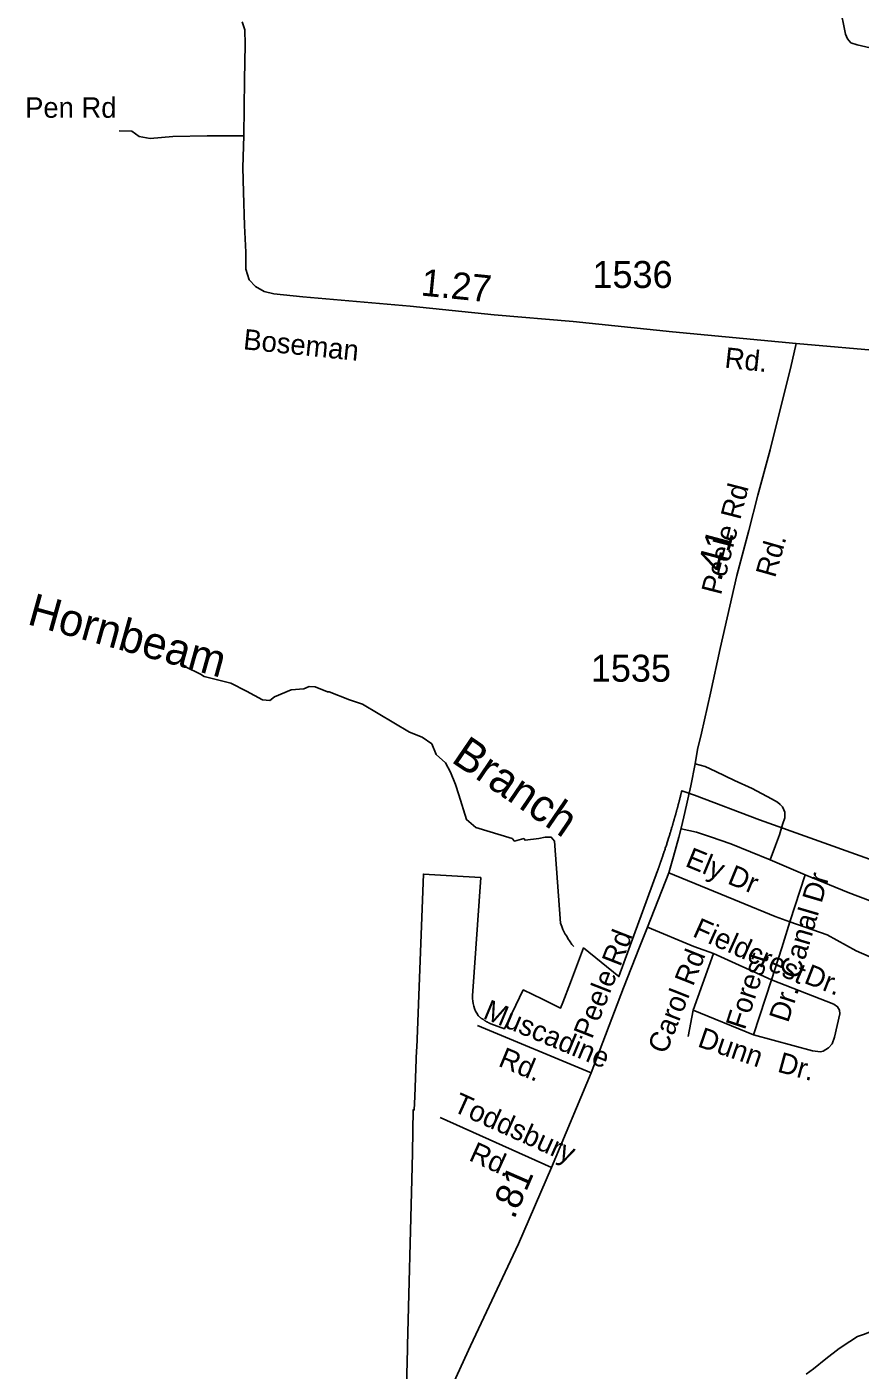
# Model space of a CAD drawing. Extents: x 2220236 to 2384410, y 720751 to 894131.
# Drawn here: x 2346680 to 2350546, y 819071 to 825303 of the extents above; entities that cross this region are included whole.
import ezdxf

# ---------------------------------------------------------------- set-up
doc = ezdxf.new("R2010")
doc.units = 0
doc.layers.add('Default', color=7, linetype='Continuous')

msp = doc.modelspace()

# ---------------------------------------------------------------- linework, layer by layer
at = {"layer": 'Default'}
for p, q in [((2350291.2, 821369.4), (2350129.4, 821438.5)), ((2350291.2, 821369.4), (2350219.5, 821151.6)), ((2349772, 820740.5), (2349866.2, 821004.9)), ((2349866.2, 821004.9), (2350134.7, 820881.7)), ((2350134.7, 820881.7), (2350051.7, 820626.8)), ((2349747.9, 820619.2), (2349772, 820740.5)), ((2350051.7, 820626.8), (2349772, 820740.5)), ((2348771.6, 820669.4), (2349298.2, 820449.8)), ((2348598.4, 820243), (2349115, 820011.9))]:
    msp.add_line(p, q, dxfattribs=at)
for points in [[(2350592.4, 825205.3), (2350533.1, 825219.2), (2350503.5, 825229.7), (2350487.8, 825247.2), (2350478.2, 825269.9), (2350452, 825399)], [(2350249.6, 823834.8), (2349675.4, 823888.9), (2349214.8, 823936.1), (2348848.4, 823967.5), (2348458.5, 824006.8), (2347960, 824051.3), (2347826.5, 824064.4), (2347780.7, 824074.9), (2347740.1, 824098.4), (2347711.3, 824129.9), (2347695.6, 824179.6), (2347695.6, 824258.2), (2347690.4, 824381.3), (2347685.2, 824535.8), (2347682.6, 824651), (2347687.1, 824797.6), (2347690.4, 825056.9), (2347693, 825221.8), (2347691.7, 825289.9), (2347678.6, 825326.6)], [(2347687.1, 824797.6), (2347517, 824797.6), (2347357.4, 824795), (2347252.7, 824784.5), (2347200.4, 824795), (2347166.4, 824818.6), (2347108.8, 824821.2)], [(2348429.1, 818509.2), (2348737.8, 819184.4), (2348961, 819657.6), (2349115, 820011.9), (2349298.2, 820449.8), (2349448.5, 820845.4), (2349523, 821034.2), (2349559.4, 821126.8), (2349658.3, 821378.4), (2349680.9, 821453.6), (2349705.3, 821544.4), (2349717.5, 821591.5), (2349733.2, 821657.9), (2349744.5, 821706.7), (2349760.2, 821782.7), (2349780.2, 821884.8), (2349791.6, 821950.3), (2349810, 822026.2), (2349851.8, 822212.1), (2349896.3, 822419), (2349974, 822757.7), (2350029.8, 822967.2), (2350071.8, 823130.2), (2350129.2, 823340.9), (2350178.1, 823539.8), (2350223.4, 823717.9), (2350249.6, 823834.8)], [(2351355.5, 823776.5), (2351251.8, 823781.3), (2351158.6, 823780.7), (2350975.6, 823783.5), (2350674.4, 823796.4), (2350249.6, 823834.8)], [(2347396.8, 822341.2), (2347409.1, 822336.8), (2347437.6, 822323.2), (2347463.7, 822311.1), (2347485.8, 822299.9), (2347502, 822289.7), (2347626.7, 822257.6), (2347699.2, 822221.4), (2347773.5, 822181.6), (2347806.6, 822178), (2347829.6, 822194.2), (2347905.7, 822226.8), (2347965.6, 822232.5), (2347989.5, 822242.4), (2348018.1, 822241.3), (2348074.2, 822218), (2348083.4, 822217.7), (2348177.5, 822181.6), (2348237.3, 822161.6), (2348454.7, 822031.2), (2348514.5, 822007.6)], [(2348514.5, 822007.6), (2348559.8, 821976.8), (2348579.7, 821927.9), (2348623.2, 821888.1), (2348645.6, 821845.1), (2348668.5, 821788.4), (2348684.8, 821739.5), (2348719.2, 821625.4), (2348762.7, 821589.1), (2348931.6, 821537.2), (2348943.3, 821525.2), (2348985.5, 821537.4), (2348991.4, 821529.4), (2349055.3, 821538.4), (2349084.2, 821543.8), (2349113.2, 821543.8), (2349127.7, 821525.7), (2349156.1, 821145.5), (2349162.3, 821129.4), (2349166.8, 821115.5), (2349172.6, 821103.6), (2349178.5, 821093.9), (2349184.8, 821084.4), (2349190.8, 821073.8), (2349201, 821057.8), (2349209.4, 821046), (2349217.3, 821036.5)], [(2349780.2, 821884.8), (2349826.7, 821872.4), (2349877.5, 821848.6), (2349963.9, 821807.5), (2350046.1, 821769.6), (2350135.8, 821722), (2350162.8, 821706.9), (2350175.8, 821696.1), (2350186.6, 821684.2), (2350193.1, 821671.2), (2350196.3, 821659.3), (2350197.4, 821643.1), (2350197.4, 821633.4), (2350186.6, 821603.1), (2350172.5, 821554.4), (2350154.2, 821505.8), (2350129.4, 821438.5)], [(2348437.8, 818870.9), (2348445.5, 819169.4), (2348446.2, 819184.9), (2348466.5, 819954.9), (2348469.5, 820077.6), (2348469.5, 820079.4), (2348472.8, 820280.1), (2348473.8, 820279.6), (2348477.2, 820277.9), (2348479.8, 820341.1), (2348488.2, 820556.1), (2348488.8, 820565.9), (2348504.5, 820971.7), (2348520.2, 821372.4), (2348704.8, 821361.1), (2348786, 821356.1), (2348748.2, 820807.2), (2348748.2, 820795.2), (2348749.2, 820783.2), (2348751, 820771.4), (2348753.8, 820759.8), (2348757.5, 820748.4), (2348762.2, 820737.3), (2348767.8, 820726.7), (2348774.2, 820716.5), (2348775.5, 820714.8), (2348776.2, 820714), (2348777.8, 820712.7), (2348780.8, 820710.2), (2348783.8, 820707.7), (2348785.5, 820706.4), (2348787, 820705.2), (2348788.5, 820704.1), (2348790, 820702.9), (2348791.8, 820701.7), (2348793.2, 820700.6), (2348795, 820699.4), (2348796.5, 820698.2), (2348798.2, 820697.2), (2348799.8, 820696.1), (2348801.5, 820695), (2348803, 820693.9), (2348804.8, 820692.9), (2348806.5, 820691.8), (2348808.2, 820690.8), (2348809.8, 820689.8), (2348811.5, 820688.8), (2348813.2, 820687.8), (2348815, 820686.9), (2348816.8, 820685.9), (2348818.5, 820685), (2348820.2, 820684.1), (2348822, 820683.2), (2348823.8, 820682.3), (2348825.5, 820681.4), (2348827.2, 820680.6), (2348829, 820679.8), (2348830.8, 820678.9), (2348832.2, 820678.4), (2348895.8, 820655.4), (2348983, 820835.1), (2349073, 820791.6), (2349156.8, 820751.1), (2349166.5, 820776.8), (2349202, 820870), (2349263, 821029.7), (2349427.2, 820896.9), (2349606.5, 821388.3), (2349607.5, 821390.6), (2349609, 821395.4), (2349610, 821397.7), (2349610.8, 821400.1), (2349611.8, 821402.4), (2349612.5, 821404.8), (2349613.2, 821407.1), (2349614.2, 821409.5), (2349615, 821411.8), (2349615.8, 821414.2), (2349616.8, 821416.6), (2349617.5, 821418.9), (2349618.2, 821421.2), (2349619.2, 821423.6), (2349620, 821426), (2349620.8, 821428.3), (2349621.8, 821430.7), (2349623.2, 821435.4), (2349624, 821437.8), (2349625, 821440.1), (2349626.5, 821444.9), (2349627.5, 821447.2), (2349628.2, 821449.6), (2349629, 821451.9), (2349630.5, 821456.7), (2349631.5, 821459.1), (2349633, 821463.8), (2349634.5, 821468.6), (2349635.5, 821470.9), (2349636.2, 821473.2), (2349637.8, 821478), (2349638.5, 821480.4), (2349639.5, 821482.8), (2349641, 821487.5), (2349642.5, 821492.2), (2349644, 821497), (2349644.8, 821499.4), (2349645.8, 821501.8), (2349647.2, 821506.5), (2349648.8, 821511.2), (2349649.5, 821513.7), (2349651, 821518.4), (2349652.5, 821523.2), (2349654, 821527.9), (2349655.5, 821532.7), (2349656.2, 821535.1), (2349657.8, 821539.9), (2349659.2, 821544.6), (2349660, 821547), (2349660.8, 821549.4), (2349661.5, 821551.8), (2349663, 821556.6), (2349663.8, 821559), (2349665.2, 821563.8), (2349666, 821566.1), (2349666.8, 821568.6), (2349667.5, 821570.9), (2349668, 821573.3), (2349668.8, 821575.7), (2349669.5, 821578.1), (2349671, 821582.9), (2349671.8, 821585.3), (2349673.2, 821590.1), (2349673.8, 821592.5), (2349675.2, 821597.2), (2349676, 821599.7), (2349676.8, 821602.1), (2349677.5, 821604.5), (2349678, 821606.9), (2349678.8, 821609.2), (2349679.5, 821611.7), (2349680.2, 821614.1), (2349680.8, 821616.5), (2349681.5, 821618.9), (2349682.2, 821621.3), (2349683.8, 821626.1), (2349684.2, 821628.5), (2349685, 821630.9), (2349685.8, 821633.3), (2349686.2, 821635.7), (2349687, 821638.1), (2349687.8, 821640.5), (2349688.5, 821642.9), (2349689, 821645.3), (2349689.8, 821647.8), (2349690.5, 821650.1), (2349691, 821652.6), (2349691.8, 821655), (2349692.5, 821657.4), (2349693, 821659.8), (2349693.8, 821662.2), (2349694.5, 821664.6), (2349695, 821667), (2349695.8, 821669.4), (2349696.5, 821671.9), (2349697, 821674.2), (2349697.8, 821676.7), (2349698.2, 821679.1), (2349699, 821681.5), (2349699.8, 821683.9), (2349700.2, 821686.3), (2349701, 821688.8), (2349701.5, 821691.2), (2349702.2, 821693.6), (2349702.8, 821696), (2349703.5, 821698.4), (2349704.2, 821700.8), (2349704.8, 821703.2), (2349705.5, 821705.7), (2349706, 821708.1), (2349706.8, 821710.5), (2349707.2, 821712.9), (2349708, 821715.4), (2349708.5, 821717.8), (2349709.2, 821720.2), (2349709.8, 821722.6), (2349710.5, 821725.1), (2349711, 821727.4), (2349711.8, 821729.9), (2349712.2, 821732.3), (2349712.8, 821734.8), (2349713.5, 821737.2), (2349714, 821739.6), (2349714.8, 821742), (2349715.2, 821744.4), (2349716, 821746.9), (2349716.5, 821749.3), (2349717, 821751.8), (2349717.8, 821754.1), (2349718.2, 821756.6), (2349719, 821759), (2349777.2, 821739.2), (2350079.2, 821624.6), (2351057, 821275.5)], [(2348437.8, 818870.9), (2348445.5, 819169.4), (2348446.2, 819184.9), (2348466.5, 819954.9), (2348469.5, 820077.6), (2348469.5, 820079.4), (2348472.8, 820280.1), (2348473.8, 820279.6), (2348477.2, 820277.9), (2348479.8, 820341.1), (2348488.2, 820556.1), (2348488.8, 820565.9), (2348504.5, 820971.7), (2348520.2, 821372.4), (2348704.8, 821361.1), (2348786, 821356.1), (2348748.2, 820807.2), (2348748.2, 820795.2), (2348749.2, 820783.2), (2348751, 820771.4), (2348753.8, 820759.8), (2348757.5, 820748.4), (2348762.2, 820737.3), (2348767.8, 820726.7), (2348774.2, 820716.5), (2348775.5, 820714.8), (2348776.2, 820714), (2348777.8, 820712.7), (2348780.8, 820710.2), (2348783.8, 820707.7), (2348785.5, 820706.4), (2348787, 820705.2), (2348788.5, 820704.1), (2348790, 820702.9), (2348791.8, 820701.7), (2348793.2, 820700.6), (2348795, 820699.4), (2348796.5, 820698.2), (2348798.2, 820697.2), (2348799.8, 820696.1), (2348801.5, 820695), (2348803, 820693.9), (2348804.8, 820692.9), (2348806.5, 820691.8), (2348808.2, 820690.8), (2348809.8, 820689.8), (2348811.5, 820688.8), (2348813.2, 820687.8), (2348815, 820686.9), (2348816.8, 820685.9), (2348818.5, 820685), (2348820.2, 820684.1), (2348822, 820683.2), (2348823.8, 820682.3), (2348825.5, 820681.4), (2348827.2, 820680.6), (2348829, 820679.8), (2348830.8, 820678.9), (2348832.2, 820678.4), (2348895.8, 820655.4), (2348983, 820835.1), (2349073, 820791.6), (2349156.8, 820751.1), (2349166.5, 820776.8), (2349202, 820870), (2349263, 821029.7), (2349427.2, 820896.9), (2349606.5, 821388.3), (2349607.5, 821390.6), (2349609, 821395.4), (2349610, 821397.7), (2349610.8, 821400.1), (2349611.8, 821402.4), (2349612.5, 821404.8), (2349613.2, 821407.1), (2349614.2, 821409.5), (2349615, 821411.8), (2349615.8, 821414.2), (2349616.8, 821416.6), (2349617.5, 821418.9), (2349618.2, 821421.2), (2349619.2, 821423.6), (2349620, 821426), (2349620.8, 821428.3), (2349621.8, 821430.7), (2349623.2, 821435.4), (2349624, 821437.8), (2349625, 821440.1), (2349626.5, 821444.9), (2349627.5, 821447.2), (2349628.2, 821449.6), (2349629, 821451.9), (2349630.5, 821456.7), (2349631.5, 821459.1), (2349633, 821463.8), (2349634.5, 821468.6), (2349635.5, 821470.9), (2349636.2, 821473.2), (2349637.8, 821478), (2349638.5, 821480.4), (2349639.5, 821482.8), (2349641, 821487.5), (2349642.5, 821492.2), (2349644, 821497), (2349644.8, 821499.4), (2349645.8, 821501.8), (2349647.2, 821506.5), (2349648.8, 821511.2), (2349649.5, 821513.7), (2349651, 821518.4), (2349652.5, 821523.2), (2349654, 821527.9), (2349655.5, 821532.7), (2349656.2, 821535.1), (2349657.8, 821539.9), (2349659.2, 821544.6), (2349660, 821547), (2349660.8, 821549.4), (2349661.5, 821551.8), (2349663, 821556.6), (2349663.8, 821559), (2349665.2, 821563.8), (2349666, 821566.1), (2349666.8, 821568.6), (2349667.5, 821570.9), (2349668, 821573.3), (2349668.8, 821575.7), (2349669.5, 821578.1), (2349671, 821582.9), (2349671.8, 821585.3), (2349673.2, 821590.1), (2349673.8, 821592.5), (2349675.2, 821597.2), (2349676, 821599.7), (2349676.8, 821602.1), (2349677.5, 821604.5), (2349678, 821606.9), (2349678.8, 821609.2), (2349679.5, 821611.7), (2349680.2, 821614.1), (2349680.8, 821616.5), (2349681.5, 821618.9), (2349682.2, 821621.3), (2349683.8, 821626.1), (2349684.2, 821628.5), (2349685, 821630.9), (2349685.8, 821633.3), (2349686.2, 821635.7), (2349687, 821638.1), (2349687.8, 821640.5), (2349688.5, 821642.9), (2349689, 821645.3), (2349689.8, 821647.8), (2349690.5, 821650.1), (2349691, 821652.6), (2349691.8, 821655), (2349692.5, 821657.4), (2349693, 821659.8), (2349693.8, 821662.2), (2349694.5, 821664.6), (2349695, 821667), (2349695.8, 821669.4), (2349696.5, 821671.9), (2349697, 821674.2), (2349697.8, 821676.7), (2349698.2, 821679.1), (2349699, 821681.5), (2349699.8, 821683.9), (2349700.2, 821686.3), (2349701, 821688.8), (2349701.5, 821691.2), (2349702.2, 821693.6), (2349702.8, 821696), (2349703.5, 821698.4), (2349704.2, 821700.8), (2349704.8, 821703.2), (2349705.5, 821705.7), (2349706, 821708.1), (2349706.8, 821710.5), (2349707.2, 821712.9), (2349708, 821715.4), (2349708.5, 821717.8), (2349709.2, 821720.2), (2349709.8, 821722.6), (2349710.5, 821725.1), (2349711, 821727.4), (2349711.8, 821729.9), (2349712.2, 821732.3), (2349712.8, 821734.8), (2349713.5, 821737.2), (2349714, 821739.6), (2349714.8, 821742), (2349715.2, 821744.4), (2349716, 821746.9), (2349716.5, 821749.3), (2349717, 821751.8), (2349717.8, 821754.1), (2349718.2, 821756.6), (2349719, 821759), (2349777.2, 821739.2), (2350079.2, 821624.6), (2351057, 821275.5)], [(2350129.4, 821438.5), (2349945.9, 821513), (2349851.4, 821545.7), (2349787.7, 821567.6), (2349715.3, 821583.2)], [(2350219.5, 821151.6), (2350151.5, 821175.1), (2349986.6, 821243.2), (2349658.3, 821378.4)], [(2350872.7, 821138.5), (2350694.6, 821209.4), (2350491.1, 821287.5), (2350291.2, 821369.4)], [(2349559.4, 821126.8), (2349774.8, 821037.3), (2349866.2, 821004.9)], [(2350134.7, 820881.7), (2350182.9, 821031.1), (2350219.5, 821151.6)], [(2350219.5, 821151.6), (2350392.9, 821091.2), (2350527.4, 821016.6), (2350647.9, 820963.2), (2350693.2, 820963), (2350706.3, 820968.3), (2350765.5, 820989.4), (2350827.3, 821074.8), (2350872.7, 821138.5)], [(2350051.7, 820626.8), (2350324.7, 820552.2), (2350362.6, 820548.5), (2350374.5, 820550.8), (2350400.3, 820567), (2350416.1, 820585.1), (2350427.7, 820615.4), (2350452.5, 820723.6), (2350450.2, 820741.6), (2350442.1, 820757.4), (2350423.8, 820769.3), (2350134.7, 820881.7)], [(2350296.5, 819052.2), (2350330.7, 819077.9), (2350387.1, 819124.1), (2350448.7, 819172), (2350498.3, 819204.5), (2350534.2, 819226.8), (2350566.7, 819238.7), (2350600.9, 819252.4), (2350660.8, 819267.8), (2350729.2, 819278.1), (2350797.6, 819286.7)]]:
    msp.add_lwpolyline(points, dxfattribs=at)

# ---------------------------------------------------------------- texts
for s, height, p in [('Horse Pen Rd', 95, (2346297.8, 824881.4)), ('1536', 125, (2349304.3, 824091.8)), ('1535', 125, (2349296.9, 822265.2))]:
    msp.add_text(s, height=height, dxfattribs=at).set_placement(p)
for s, height, rotation, p in [('1.27', 125, 354.21531, (2348505.1, 824057.3)), ('Boseman', 95, 354.21531, (2347681.3, 823807.7)), ('Rd.', 95, 353.80621, (2349914.7, 823722.6)), ('Peele Rd', 95, 75.57576, (2349900.1, 822663.5)), ('.41', 125, 75.07762, (2349900.7, 822725.7)), ('Rd.', 95, 74.15741, (2350151.6, 822743.5)), ('Hornbeam', 150, 344.52666, (2346676.6, 822533.1)), ('Branch', 150, 325.72596, (2348643.9, 821895.9)), ('Ely Dr', 95, 337.5799, (2349730.1, 821411)), ('Canal Dr', 95, 73.63606, (2350263.5, 820881.4)), ('Peele Rd', 95, 68.67944, (2349302.2, 820603.7)), ('Fieldcrest', 95, 335.90895, (2349764.1, 821085.7)), ('Carol Rd', 95, 68.35393, (2349645.7, 820533.4)), ('Forest', 95, 71.96419, (2350011, 820645.9)), ('Dr.', 95, 338.75408, (2350281.1, 820868.7)), ('Dr.', 95, 71.96419, (2350211.8, 820679.2)), ('Muscadine', 95, 337.36321, (2348791.7, 820705.4)), ('Dunn', 95, 340.9721, (2349787.6, 820574)), ('Rd.', 95, 337.36321, (2348862.6, 820484)), ('Dr.', 95, 344.71645, (2350158.3, 820456.6)), ('Toddsbury', 95, 335.70396, (2348651.1, 820274.6)), ('Rd.', 95, 335.70396, (2348726, 820046.6)), ('.81', 125, 66.51479, (2348940.7, 819767.7))]:
    msp.add_text(s, height=height, rotation=rotation, dxfattribs=at).set_placement(p)

doc.saveas('drawing.dxf')
